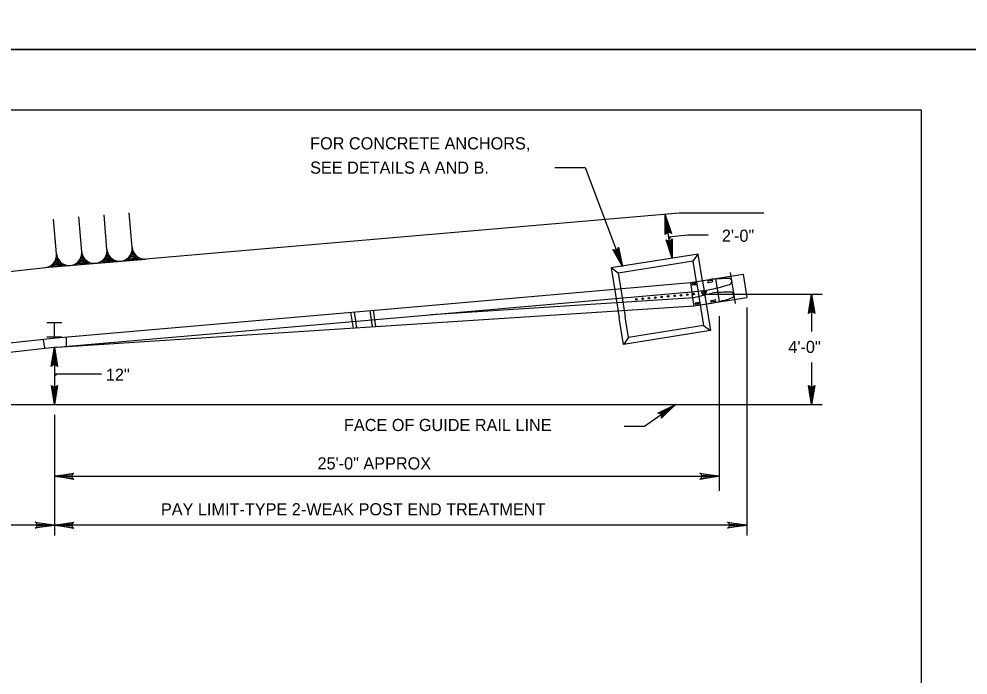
# Model space of a CAD drawing. Extents: x 637628 to 640188, y 298266 to 300751.
# Drawn here: x 638881.6 to 639116, y 298705.1 to 298867.1 of the extents above; entities that cross this region are included whole.
import ezdxf

# ---------------------------------------------------------------- set-up
doc = ezdxf.new("R2010")
doc.units = 0
for name, color, linetype in [('1', 7, 'Continuous'), ('2', 7, 'Continuous'), ('3', 7, 'Continuous'), ('PLT-BNDY', 7, 'Continuous')]:
    doc.layers.add(name, color=color, linetype=linetype)

msp = doc.modelspace()

# ---------------------------------------------------------------- linework, layer by layer
at = {"layer": '1'}
msp.add_lwpolyline([(639104.52, 298280.58), (639104.52, 298844.55), (638318.55, 298844.55), (638318.55, 298280.58), (639104.52, 298280.58), (639104.52, 298306.93), (638904.53, 298306.93), (638904.53, 298371.61), (639104.52, 298371.61), (639104.52, 298400.57), (638904.53, 298400.57), (638904.53, 298280.58), (638983.33, 298280.58), (638983.33, 298306.93), (638983.33, 298280.58), (639060.33, 298280.58), (639060.33, 298306.93), (639060.33, 298294.62), (639104.52, 298294.62)], dxfattribs=at)
at = {"layer": '2'}
for p, q in [((638888.04, 298805.71), (639044.63, 298819.23)), ((638890.89, 298809.08), (638890.17, 298817.66)), ((638897.12, 298809.61), (638896.39, 298818.19)), ((638903.34, 298810.13), (638902.62, 298818.71)), ((638909.57, 298810.66), (638908.85, 298819.24)), ((639042.94, 298807.99), (639041.24, 298818.69)), ((639044.63, 298819.24), (639065.54, 298819.24)), ((639048.13, 298807.29), (639049.38, 298809.02)), ((638802.61, 298796.38), (638888.87, 298805.76)), ((639029.59, 298804.33), (639027.85, 298805.59)), ((639047.44, 298801.97), (639060.45, 298804.05)), ((639058.57, 298796.81), (639057.34, 298804.51)), ((639060.45, 298804.05), (639061.37, 298798.31)), ((638978.08, 298795.9), (639047.44, 298801.97)), ((639047.44, 298801.97), (639047.9, 298799.1)), ((639047.44, 298801.97), (639047.44, 298801.97)), ((639048.89, 298801.9), (639048, 298801.76)), ((639048.07, 298801.39), (639048.96, 298801.52)), ((639048.32, 298801.64), (639048.47, 298801.81)), ((639048.4, 298801.49), (639048.32, 298801.64)), ((639048.47, 298801.81), (639048.33, 298801.54)), ((639048.33, 298801.54), (639048.63, 298801.7)), ((639048.49, 298801.48), (639048.36, 298801.75)), ((639048.36, 298801.75), (639048.4, 298801.49)), ((639048.53, 298801.52), (639048.42, 298801.8)), ((639048.42, 298801.8), (639048.49, 298801.48)), ((639048.63, 298801.7), (639048.46, 298801.47)), ((639048.46, 298801.47), (639048.63, 298801.56)), ((639048.48, 298801.64), (639048.48, 298801.64)), ((639048.48, 298801.64), (639048.48, 298801.64)), ((639048.48, 298801.64), (639048.48, 298801.64)), ((639048.61, 298801.59), (639048.5, 298801.8)), ((639048.5, 298801.8), (639048.53, 298801.52)), ((639048.58, 298801.77), (639048.61, 298801.59)), ((639048.94, 298802.21), (639049.86, 298796.47)), ((639050.43, 298802.45), (639051.35, 298796.71)), ((639052.72, 298802.51), (639051.82, 298802.37)), ((639051.9, 298802), (639052.78, 298802.14)), ((639052.3, 298802.25), (639052.3, 298802.25)), ((639052.3, 298802.25), (639052.3, 298802.25)), ((639053.67, 298802.87), (639054.55, 298797.35)), ((639055.26, 298801.99), (639055.26, 298801.99)), ((639055.26, 298801.99), (639055.26, 298801.99)), ((639055.42, 298801.04), (639055.42, 298801.04)), ((639056.94, 298802.26), (639056.94, 298802.26)), ((638978.28, 298793.61), (639047.7, 298799.69)), ((639028.9, 298799.01), (639029.82, 298793.27)), ((639030.4, 298799.25), (639031.32, 298793.51)), ((639047.7, 298799.69), (639051.44, 298800.14)), ((639048.36, 298796.23), (639047.9, 298799.1)), ((639047.98, 298798.26), (639052.76, 298799.38)), ((639051.19, 298799.82), (639050.29, 298799.67)), ((639050.31, 298799.68), (639051.19, 298799.82)), ((639051.25, 298799.44), (639050.35, 298799.3)), ((639050.37, 298799.3), (639051.25, 298799.44)), ((639050.4, 298799.1), (639080.01, 298799.1)), ((639050.77, 298799.56), (639050.77, 298799.56)), ((639050.77, 298799.56), (639050.77, 298799.56)), ((639051.44, 298800.14), (639052.61, 298800.34)), ((639055.64, 298799.6), (639055.64, 298799.6)), ((639055.8, 298798.64), (639055.8, 298798.64)), ((639055.8, 298798.64), (639055.8, 298798.64)), ((639057.47, 298798.91), (639057.47, 298798.91)), ((639077.38, 298799.1), (639077.38, 298789.9)), ((638891.03, 298786), (639048.36, 298796.23)), ((638983.45, 298794.07), (639048.23, 298798.28)), ((639048.36, 298796.23), (639053.14, 298796.99)), ((639048.36, 298796.23), (639048.36, 298796.23)), ((639048.78, 298796.98), (639049.66, 298797.12)), ((639049.72, 298796.74), (639048.82, 298796.6)), ((639049.08, 298796.85), (639049.23, 298797.02)), ((639049.17, 298796.7), (639049.08, 298796.85)), ((639049.23, 298797.02), (639049.09, 298796.75)), ((639049.09, 298796.75), (639049.4, 298796.91)), ((639049.25, 298796.7), (639049.12, 298796.97)), ((639049.12, 298796.97), (639049.17, 298796.7)), ((639049.29, 298796.74), (639049.19, 298797.01)), ((639049.19, 298797.01), (639049.25, 298796.7)), ((639049.4, 298796.91), (639049.22, 298796.69)), ((639049.22, 298796.69), (639049.4, 298796.77)), ((639049.24, 298796.86), (639049.24, 298796.86)), ((639049.24, 298796.86), (639049.24, 298796.86)), ((639049.24, 298796.86), (639049.24, 298796.86)), ((639049.37, 298796.8), (639049.26, 298797.01)), ((639049.26, 298797.01), (639049.29, 298796.74)), ((639049.34, 298796.98), (639049.37, 298796.8)), ((639051.35, 298796.71), (639061.37, 298798.31)), ((639052.6, 298797.59), (639053.49, 298797.73)), ((639053.55, 298797.35), (639052.65, 298797.21)), ((639053.07, 298797.47), (639053.07, 298797.47)), ((639053.07, 298797.47), (639053.07, 298797.47)), ((638890.76, 298788.36), (638978.08, 298795.9)), ((638963.51, 298794.64), (638964.12, 298790.75)), ((638964.36, 298794.72), (638964.98, 298790.81)), ((638968.25, 298795.03), (638968.87, 298791.06)), ((638969.06, 298795.12), (638969.68, 298791.11)), ((638983.45, 298794.07), (638983.45, 298794.07)), ((639054.56, 298793.72), (639054.56, 298750.53)), ((639061.37, 298795.81), (639061.37, 298739.57)), ((638888.51, 298792.13), (638892.16, 298792.13)), ((638890.37, 298788.56), (638890.37, 298792.14)), ((638890.96, 298786.07), (638978.28, 298793.61)), ((638966.45, 298791.79), (638966.45, 298791.79)), ((639050.67, 298791.38), (639052.4, 298790.13)), ((638804.5, 298778.98), (638890.76, 298788.36)), ((638887.58, 298787.85), (638887.93, 298785.76)), ((638888.51, 298788.56), (638892.16, 298788.56)), ((638890.38, 298788.59), (638890.38, 298788.59)), ((638893.25, 298788.6), (638893.28, 298786.09)), ((639032.13, 298788.42), (639030.87, 298786.69)), ((638804.75, 298776.7), (638891.01, 298786.08)), ((638890.37, 298786.01), (638890.37, 298771.84)), ((639077.38, 298782.26), (639077.38, 298771.84)), ((638902.03, 298779.37), (638890.37, 298779.37)), ((638726.82, 298771.84), (639080.01, 298771.84)), ((638726.96, 298771.84), (638892.87, 298771.84)), ((638890.37, 298769.34), (638890.37, 298739.57)), ((638890.37, 298754.16), (638951.39, 298754.16)), ((638951.39, 298754.16), (639054.55, 298754.16)), ((638890.37, 298742.07), (638793.01, 298742.07)), ((638954.71, 298742.07), (638890.37, 298742.07)), ((639061.37, 298742.07), (638954.71, 298742.07))]:
    msp.add_line(p, q, dxfattribs=at)
for points in [[(639013.98, 298830.44), (639021.48, 298830.44), (639030.69, 298805.99)], [(639041.39, 298814.11), (639041.69, 298814.33), (639041.24, 298818.69), (639041.39, 298814.11), (639041.23, 298813.85), (639041.24, 298818.69), (639042.14, 298814.41), (639042.48, 298814.3), (639041.24, 298818.69), (639042.74, 298814.09), (639042.48, 298814.3)], [(639042.79, 298812.56), (639042.49, 298812.34), (639042.94, 298807.99), (639042.79, 298812.56), (639042.95, 298812.82), (639042.94, 298807.99), (639042.04, 298812.26), (639041.7, 298812.37), (639042.94, 298807.99), (639041.44, 298812.58), (639041.7, 298812.37)], [(639051.82, 298813.71), (639046.82, 298813.71), (639041.97, 298813.2)], [(639029.6, 298810.44), (639029.35, 298810.16), (639030.69, 298805.99), (639029.6, 298810.44), (639029.7, 298810.73), (639030.69, 298805.99), (639028.93, 298810), (639028.57, 298810.03), (639030.69, 298805.99), (639028.28, 298810.18), (639028.57, 298810.03)], [(638888.04, 298805.71), (638912.95, 298807.8)], [(638889.61, 298806.01), (638890.43, 298806.63), (638890.95, 298807.91)], [(638889.67, 298806.11), (638892.52, 298806.32), (638890.2, 298806.44), (638891.9, 298806.68), (638890.51, 298806.79), (638891.45, 298807.13), (638890.88, 298807.3), (638891.28, 298807.48), (638890.92, 298807.74), (638890.94, 298808.06), (638891.74, 298806.62), (638892.57, 298806.3)], [(638895.9, 298806.51), (638896.72, 298807.14), (638897.24, 298808.42)], [(638895.98, 298806.66), (638898.83, 298806.88), (638896.51, 298807), (638898.21, 298807.24), (638896.82, 298807.34), (638897.76, 298807.69), (638897.19, 298807.86), (638897.59, 298808.04), (638897.23, 298808.3), (638897.25, 298808.61), (638898.05, 298807.18), (638898.88, 298806.86)], [(638902.14, 298807.21), (638904.99, 298807.42), (638902.68, 298807.54), (638904.38, 298807.78), (638902.99, 298807.88), (638903.93, 298808.23), (638903.36, 298808.4), (638903.75, 298808.58), (638903.39, 298808.84), (638903.41, 298809.16), (638904.21, 298807.72), (638905.04, 298807.4)], [(638902.15, 298807.16), (638902.97, 298807.79), (638903.49, 298809.07)], [(638908.32, 298807.63), (638909.14, 298808.26), (638909.66, 298809.54)], [(638908.41, 298807.71), (638911.26, 298807.92), (638908.94, 298808.05), (638910.64, 298808.29), (638909.25, 298808.39), (638910.19, 298808.73), (638909.62, 298808.9), (638910.02, 298809.08), (638909.66, 298809.34), (638909.68, 298809.66), (638910.48, 298808.22), (638911.31, 298807.9)], [(639050.43, 298802.45), (639049.38, 298809.02), (639027.85, 298805.59), (639028.9, 298799.01)], [(639048.94, 298802.21), (639048.13, 298807.29), (639029.59, 298804.33), (639030.4, 298799.25)], [(639076.81, 298794.56), (639077.14, 298794.73), (639077.38, 298799.1), (639076.81, 298794.56), (639076.62, 298794.32), (639077.38, 298799.1), (639077.6, 298794.73), (639077.93, 298794.57), (639077.38, 298799.1), (639078.14, 298794.32), (639077.93, 298794.57)], [(639051.35, 298796.71), (639052.4, 298790.13), (639030.87, 298786.69), (639029.82, 298793.27)], [(639049.86, 298796.47), (639050.67, 298791.38), (639032.13, 298788.42), (639031.32, 298793.51)], [(638889.8, 298781.47), (638890.13, 298781.64), (638890.37, 298786.01), (638889.8, 298781.47), (638889.6, 298781.24), (638890.37, 298786.01), (638890.59, 298781.65), (638890.91, 298781.49), (638890.37, 298786.01), (638891.13, 298781.24), (638890.91, 298781.49)], [(638890.94, 298776.38), (638890.61, 298776.21), (638890.37, 298771.84), (638890.94, 298776.38), (638891.14, 298776.61), (638890.37, 298771.84), (638890.15, 298776.21), (638889.83, 298776.37), (638890.37, 298771.84), (638889.61, 298776.61), (638889.83, 298776.37)], [(639077.95, 298776.38), (639077.63, 298776.21), (639077.38, 298771.84), (639077.95, 298776.38), (639078.15, 298776.61), (639077.38, 298771.84), (639077.17, 298776.21), (639076.84, 298776.37), (639077.38, 298771.84), (639076.63, 298776.61), (639076.84, 298776.37)], [(639031.11, 298766.56), (639036.11, 298766.56), (639043.75, 298771.84)], [(639039.69, 298769.73), (639040.02, 298769.55), (639043.75, 298771.84), (639039.69, 298769.73), (639039.39, 298769.76), (639043.75, 298771.84), (639040.28, 298769.18), (639040.33, 298768.82), (639043.75, 298771.84), (639040.26, 298768.5), (639040.33, 298768.82)], [(638894.91, 298753.59), (638894.74, 298753.92), (638890.37, 298754.16), (638894.91, 298753.59), (638895.14, 298753.39), (638890.37, 298754.16), (638894.74, 298754.37), (638894.9, 298754.7), (638890.37, 298754.16), (638895.14, 298754.92), (638894.9, 298754.7)], [(639050.01, 298754.73), (639050.18, 298754.4), (639054.55, 298754.16), (639050.01, 298754.73), (639049.78, 298754.93), (639054.55, 298754.16), (639050.18, 298753.94), (639050.02, 298753.62), (639054.55, 298754.16), (639049.78, 298753.4), (639050.02, 298753.62)], [(638885.83, 298742.64), (638886, 298742.31), (638890.37, 298742.07), (638885.83, 298742.64), (638885.6, 298742.84), (638890.37, 298742.07), (638886, 298741.86), (638885.84, 298741.53), (638890.37, 298742.07), (638885.6, 298741.31), (638885.84, 298741.53)], [(638894.91, 298741.5), (638894.74, 298741.83), (638890.37, 298742.07), (638894.91, 298741.5), (638895.14, 298741.3), (638890.37, 298742.07), (638894.74, 298742.29), (638894.9, 298742.61), (638890.37, 298742.07), (638895.14, 298742.83), (638894.9, 298742.61)], [(639056.83, 298742.64), (639057, 298742.31), (639061.37, 298742.07), (639056.83, 298742.64), (639056.6, 298742.84), (639061.37, 298742.07), (639057, 298741.86), (639056.84, 298741.53), (639061.37, 298742.07), (639056.6, 298741.31), (639056.84, 298741.53)]]:
    msp.add_lwpolyline(points, dxfattribs=at)
for centre, radius in [((639048.48, 298801.64), 0.197), ((639038.78, 298798.28), 0.191), ((639040.36, 298798.43), 0.191), ((639041.94, 298798.57), 0.191), ((639043.52, 298798.72), 0.191), ((639045.09, 298798.86), 0.191), ((639046.66, 298799.01), 0.191), ((639048.23, 298799.15), 0.191), ((639034.07, 298797.85), 0.191), ((639035.64, 298797.99), 0.191), ((639037.21, 298798.14), 0.191), ((639049.24, 298796.86), 0.197)]:
    msp.add_circle(centre, radius, dxfattribs=at)
for centre, radius, start, end in [((638900.23, 298809.87), 3.13, 184.813, 4.813), ((638906.46, 298810.39), 3.13, 184.813, 4.813), ((638912.69, 298810.92), 3.13, 184.813, 274.813), ((638887.78, 298808.82), 3.13, 274.813, 4.813), ((638894, 298809.35), 3.13, 184.813, 4.813), ((639048.04, 298801.57), 0.192, 102.2516, 280.3511), ((639048.92, 298801.71), 0.192, 279.7038, 97.8166), ((639051.87, 298802.19), 0.192, 102.2516, 280.3511), ((639056.62, 298763.28), 39.7, 89.7089, 96.3542), ((639044.49, 298839.2), 39.7, 281.7962, 288.4416), ((639052.75, 298802.33), 0.192, 279.7038, 97.8166), ((639056.94, 298802.26), 0.727, 279.0752, 99.0752), ((639050.34, 298799.49), 0.192, 97.7993, 275.8988), ((639050.34, 298799.49), 0.192, 102.2516, 280.3511), ((639051.22, 298799.63), 0.192, 280.3338, 98.4466), ((639051.22, 298799.63), 0.192, 279.7038, 97.8166), ((639057.16, 298759.93), 39.7, 89.7089, 96.3542), ((639057.47, 298798.91), 0.727, 279.0752, 99.0752), ((639048.8, 298796.79), 0.192, 97.7993, 275.8988), ((639049.69, 298796.93), 0.192, 280.3338, 98.4466), ((639052.63, 298797.4), 0.192, 97.7993, 275.8988), ((639045.03, 298835.85), 39.7, 281.7962, 288.4416), ((639053.51, 298797.54), 0.192, 280.3338, 98.4466)]:
    msp.add_arc(centre, radius, start, end, dxfattribs=at)
at = {"layer": 'PLT-BNDY'}
for points in [[(638278.52, 299453.58), (639119.52, 299453.58), (639119.52, 298859.58), (638278.52, 298859.58)], [(638278.52, 298859.58), (639119.52, 298859.58), (639119.52, 298265.58), (638278.52, 298265.58)]]:
    msp.add_lwpolyline(points, close=True, dxfattribs=at)

# ---------------------------------------------------------------- texts
at = {"layer": '1'}
msp.add_text('4\'-0"', height=3, dxfattribs=at).set_placement((639071.62, 298784.6))
at = {"layer": '3'}
for s, height, p in [('FOR CONCRETE ANCHORS,', 3, (638953.52, 298834.87)), ('SEE DETAILS A AND B.', 3, (638953.52, 298828.87)), ('2\'-0"', 3, (639055.21, 298812.06)), ('.', 3, (639041.85, 298812.81)), ('.', 1.72, (638964.49, 298792.61)), ('.', 1.72, (638964.61, 298791.75)), ('.', 1.72, (638968.33, 298793.17)), ('.', 1.72, (638968.49, 298792.15)), ('.', 1.72, (638968.63, 298791.21)), ('.', 1.72, (638964.76, 298790.91)), ('12"', 3, (638903.08, 298777.73)), ('.', 3, (638889.95, 298778.92)), ('.', 3, (638890.23, 298779.06)), ('FACE OF GUIDE RAIL LINE', 3, (638961.88, 298765.32)), ('25\'-0" APPROX', 3, (638955.34, 298755.84)), ('PAY LIMIT-TYPE 2-WEAK POST END TREATMENT', 3, (638916.67, 298744.51))]:
    msp.add_text(s, height=height, dxfattribs=at).set_placement(p)
for p in [(638964.36, 298793.47), (638968.18, 298794.1)]:
    msp.add_text('.', height=1.72, rotation=356.0127, dxfattribs=at).set_placement(p)

doc.saveas('drawing.dxf')
